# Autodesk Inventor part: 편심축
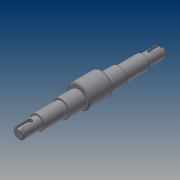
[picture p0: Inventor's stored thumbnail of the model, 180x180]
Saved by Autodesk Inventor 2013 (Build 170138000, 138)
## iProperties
Created: 2014-12
Part Number: 편심축
Material: Generic
Document SubType Name: Modeling
Designer: H1
Density: 1 g/cm^3
Author: H1
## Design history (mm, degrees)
sketch "스케치1"
  geometry: L1 (-75.5, 0)-(75.5, 0); L2 (-75.5, 0)-(-75.5, 6); L3 (-75.5, 6)-(-55.5, 6); L4 (-55.5, 6)-(-55.5, 7.5); L5 (-55.5, 7.5)-(-30.5, 7.5); L6 (-30.5, 7.5)-(-30.5, 9); L7 (-30.5, 9)-(-14.78, 9); L8 (-14.78, 9)-(30.5, 9); L9 (30.5, 9)-(30.5, 7.5); L10 (30.5, 7.5)-(55.5, 7.5); L11 (55.5, 7.5)-(55.5, 6); L12 (55.5, 6)-(75.5, 6); L13 (75.5, 6)-(75.5, 0); L14 (-12.5, 2)-(12.5, 2); L15 (12.5, 2)-(12.5, 14); L16 (12.5, 14)-(-12.5, 14); L17 (-12.5, 14)-(-12.5, 2); 2 further points
  constraints: 34 end point, 10 parallel, 5 perpendicular, 3 collinear, 1 coincident, 1 horizontal, 1 midpoint
  dimensions: "d4" = 151 distance of L1.start L1.end; "d6" = 18 diameter of L8 L1; "d7" = 15 diameter of L5 L1; "d8" = 12 diameter of L3 L1; "d9" = 20 distance of L2.end L3.end; "d10" = 25 distance of L4.end L5.end; "d11" = 20 distance of L11.end L12.end; "d12" = 25 distance of L9.end L10.end; "d13" = 2 distance between parallel lines of L14 L1; "d14" = 18 distance between parallel lines of L15 L9; "d15" = 18 distance between parallel lines of L17 L6; "d16" = 24 diameter of L16 L14
revolve "회전1" stored, may be unused: angle "d17" = 90 deg
revolve "회전2" stored, may be unused: angle "d18" = 90 deg
node "작업 평면1"
sketch "스케치2"
  geometry: L1 (75.5, 6)-(75.5, -6) reference; L2 (75.5, -2.5)-(64, -2.5); L3 (61.5, 0)-(61.5, 0); L4 (64, 2.5)-(75.5, 2.5); L5 (75.5, 2.5)-(75.5, -2.5); L6 (-75.5, 6)-(-75.5, -6) reference; L7 (0, 10.042)-(0, 6); L8 (-75.5, -2.5)-(-64, -2.5); L9 (-61.5, 0)-(-61.5, 0); L10 (-64, 2.5)-(-75.5, 2.5); L11 (-75.5, 2.5)-(-75.5, -2.5); A1 r 2.5 centre (64, 0) between (64, 2.5) and (61.5, 0); A2 r 2.5 centre (64, 0) between (61.5, 0) and (64, -2.5); A3 r 2.5 centre (-64, 0) between (-61.5, 0) and (-64, 2.5); A4 r 2.5 centre (-64, 0) between (-64, -2.5) and (-61.5, 0); 5 further points
  constraints: 18 end point, 8 point on circle, 8 tangent, 5 parallel, 4 centre point, 4 midpoint, 2 coincident, 2 concentric, 2 horizontal, 2 perpendicular, 2 point on line
  dimensions: "d20" = 5 distance of L4.end L2.start; "d22" = 14 distance between parallel lines of L3 L1; "d23" = 2.5 radius of A1; "d24" = 5 distance of L10.end L8.start; "d25" = 14 distance between parallel lines of L9 L11; "d26" = 2.5 radius of A3
extrude "돌출1" cut sketch "스케치2" distance "d27" = 3; taper "d28" = 0 deg
chamfer "모따기1" distance "d29" = 1; stored, may be unused: second distance "d30" = 2, angle "d31" = 45 deg
node "솔리드1"
other parameters: "d19" = 6
